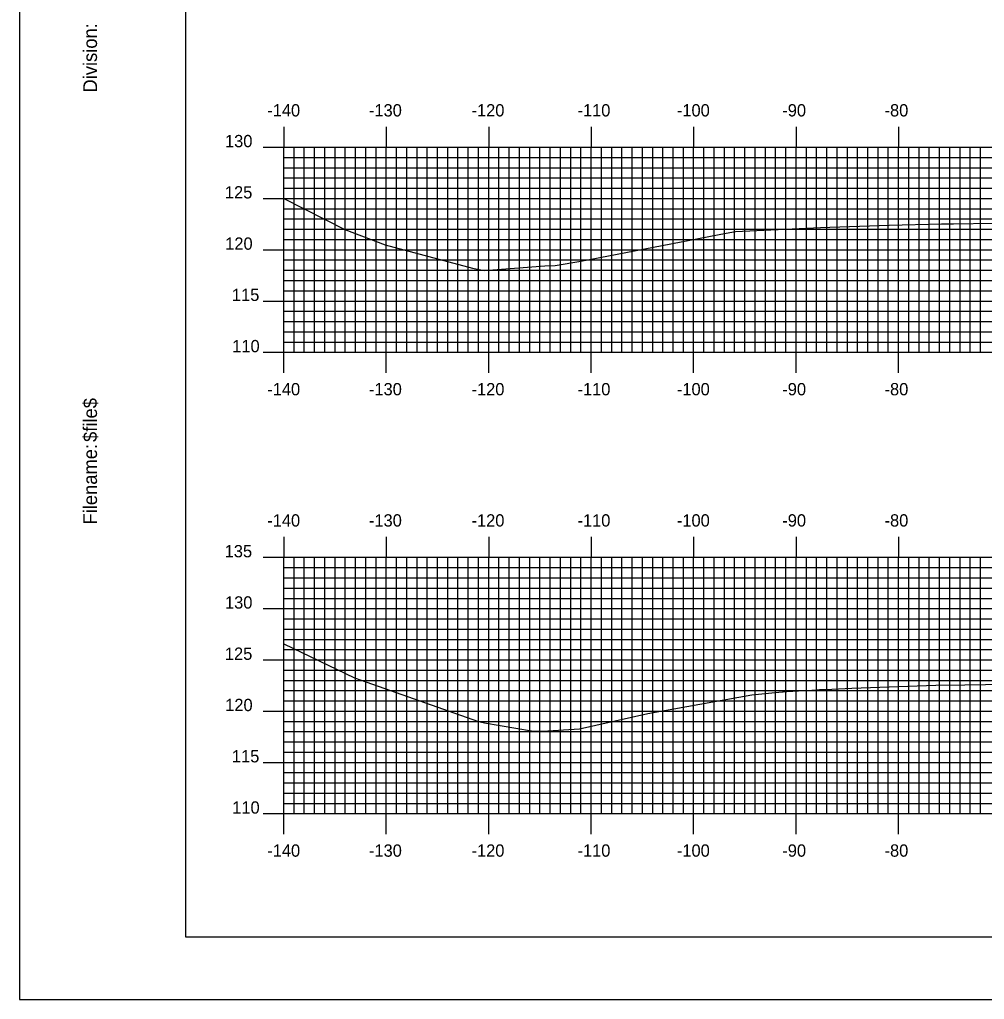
# Model space of a CAD drawing. Extents: x 853894 to 854237, y 366605 to 366825.
# Drawn here: x 853893.7 to 853987.9, y 366604.9 to 366700.5 of the extents above; entities that cross this region are included whole.
import ezdxf

# ---------------------------------------------------------------- set-up
doc = ezdxf.new("R2010")
doc.units = 0
for name, color, linetype in [('BORDER', 7, 'Continuous'), ('H_V ANNOTATION', 7, 'Continuous'), ('M_Roadway_Centerline', 7, 'Continuous'), ('MAJOR', 7, 'Continuous'), ('MINOR', 7, 'Continuous'), ('PLOT BOUNDARY', 7, 'Continuous'), ('S_Roadway_Centerline', 7, 'Continuous')]:
    doc.layers.add(name, color=color, linetype=linetype)

msp = doc.modelspace()

# ---------------------------------------------------------------- linework, layer by layer
at = {"layer": 'BORDER'}
msp.add_lwpolyline([(853909.93, 366611.055), (854229.93, 366611.055), (854229.93, 366821.055), (853909.93, 366821.055)], close=True, dxfattribs=at)
at = {"layer": 'MAJOR'}
for p, q in [((853919.53, 366690.059), (853919.53, 366688.055)), ((853929.53, 366690.059), (853929.53, 366688.055)), ((853939.53, 366690.059), (853939.53, 366688.055)), ((853949.53, 366690.059), (853949.53, 366688.055)), ((853959.53, 366690.059), (853959.53, 366688.055)), ((853969.53, 366690.059), (853969.53, 366688.055)), ((853979.53, 366690.059), (853979.53, 366688.055)), ((853917.526, 366688.055), (853919.53, 366688.055)), ((853919.53, 366688.055), (854199.53, 366688.055)), ((853919.53, 366668.055), (853919.53, 366688.055)), ((853919.53, 366668.055), (853919.53, 366688.055)), ((853919.53, 366688.055), (854199.53, 366688.055)), ((853929.53, 366668.055), (853929.53, 366688.055)), ((853939.53, 366668.055), (853939.53, 366688.055)), ((853949.53, 366668.055), (853949.53, 366688.055)), ((853959.53, 366668.055), (853959.53, 366688.055)), ((853969.53, 366668.055), (853969.53, 366688.055)), ((853979.53, 366668.055), (853979.53, 366688.055)), ((853917.526, 366683.055), (853919.53, 366683.055)), ((853919.53, 366683.055), (854199.53, 366683.055)), ((853917.526, 366678.055), (853919.53, 366678.055)), ((853919.53, 366678.055), (854199.53, 366678.055)), ((853917.526, 366673.055), (853919.53, 366673.055)), ((853919.53, 366673.055), (854199.53, 366673.055)), ((853917.526, 366668.055), (853919.53, 366668.055)), ((853919.53, 366668.055), (854199.53, 366668.055)), ((853919.53, 366668.055), (854199.53, 366668.055)), ((853919.53, 366666.051), (853919.53, 366668.055)), ((853929.53, 366666.051), (853929.53, 366668.055)), ((853939.53, 366666.051), (853939.53, 366668.055)), ((853949.53, 366666.051), (853949.53, 366668.055)), ((853959.53, 366666.051), (853959.53, 366668.055)), ((853969.53, 366666.051), (853969.53, 366668.055)), ((853979.53, 366666.051), (853979.53, 366668.055)), ((853919.53, 366650.059), (853919.53, 366648.055)), ((853929.53, 366650.059), (853929.53, 366648.055)), ((853939.53, 366650.059), (853939.53, 366648.055)), ((853949.53, 366650.059), (853949.53, 366648.055)), ((853959.53, 366650.059), (853959.53, 366648.055)), ((853969.53, 366650.059), (853969.53, 366648.055)), ((853979.53, 366650.059), (853979.53, 366648.055)), ((853917.526, 366648.055), (853919.53, 366648.055)), ((853919.53, 366648.055), (854199.53, 366648.055)), ((853919.53, 366623.055), (853919.53, 366648.055)), ((853919.53, 366623.055), (853919.53, 366648.055)), ((853919.53, 366648.055), (854199.53, 366648.055)), ((853929.53, 366623.055), (853929.53, 366648.055)), ((853939.53, 366623.055), (853939.53, 366648.055)), ((853949.53, 366623.055), (853949.53, 366648.055)), ((853959.53, 366623.055), (853959.53, 366648.055)), ((853969.53, 366623.055), (853969.53, 366648.055)), ((853979.53, 366623.055), (853979.53, 366648.055)), ((853917.526, 366643.055), (853919.53, 366643.055)), ((853919.53, 366643.055), (854199.53, 366643.055)), ((853917.526, 366638.055), (853919.53, 366638.055)), ((853919.53, 366638.055), (854199.53, 366638.055)), ((853917.526, 366633.055), (853919.53, 366633.055)), ((853919.53, 366633.055), (854199.53, 366633.055)), ((853917.526, 366628.055), (853919.53, 366628.055)), ((853919.53, 366628.055), (854199.53, 366628.055)), ((853917.526, 366623.055), (853919.53, 366623.055)), ((853919.53, 366623.055), (854199.53, 366623.055)), ((853919.53, 366623.055), (854199.53, 366623.055)), ((853919.53, 366621.051), (853919.53, 366623.055)), ((853929.53, 366621.051), (853929.53, 366623.055)), ((853939.53, 366621.051), (853939.53, 366623.055)), ((853949.53, 366621.051), (853949.53, 366623.055)), ((853959.53, 366621.051), (853959.53, 366623.055)), ((853969.53, 366621.051), (853969.53, 366623.055)), ((853979.53, 366621.051), (853979.53, 366623.055))]:
    msp.add_line(p, q, dxfattribs=at)
at = {"layer": 'MINOR'}
for p, q in [((853920.53, 366668.055), (853920.53, 366688.055)), ((853921.53, 366668.055), (853921.53, 366688.055)), ((853922.53, 366668.055), (853922.53, 366688.055)), ((853923.53, 366668.055), (853923.53, 366688.055)), ((853924.53, 366668.055), (853924.53, 366688.055)), ((853925.53, 366668.055), (853925.53, 366688.055)), ((853926.53, 366668.055), (853926.53, 366688.055)), ((853927.53, 366668.055), (853927.53, 366688.055)), ((853928.53, 366668.055), (853928.53, 366688.055)), ((853930.53, 366668.055), (853930.53, 366688.055)), ((853931.53, 366668.055), (853931.53, 366688.055)), ((853932.53, 366668.055), (853932.53, 366688.055)), ((853933.53, 366668.055), (853933.53, 366688.055)), ((853934.53, 366668.055), (853934.53, 366688.055)), ((853935.53, 366668.055), (853935.53, 366688.055)), ((853936.53, 366668.055), (853936.53, 366688.055)), ((853937.53, 366668.055), (853937.53, 366688.055)), ((853938.53, 366668.055), (853938.53, 366688.055)), ((853940.53, 366668.055), (853940.53, 366688.055)), ((853941.53, 366668.055), (853941.53, 366688.055)), ((853942.53, 366668.055), (853942.53, 366688.055)), ((853943.53, 366668.055), (853943.53, 366688.055)), ((853944.53, 366668.055), (853944.53, 366688.055)), ((853945.53, 366668.055), (853945.53, 366688.055)), ((853946.53, 366668.055), (853946.53, 366688.055)), ((853947.53, 366668.055), (853947.53, 366688.055)), ((853948.53, 366668.055), (853948.53, 366688.055)), ((853950.53, 366668.055), (853950.53, 366688.055)), ((853951.53, 366668.055), (853951.53, 366688.055)), ((853952.53, 366668.055), (853952.53, 366688.055)), ((853953.53, 366668.055), (853953.53, 366688.055)), ((853954.53, 366668.055), (853954.53, 366688.055)), ((853955.53, 366668.055), (853955.53, 366688.055)), ((853956.53, 366668.055), (853956.53, 366688.055)), ((853957.53, 366668.055), (853957.53, 366688.055)), ((853958.53, 366668.055), (853958.53, 366688.055)), ((853960.53, 366668.055), (853960.53, 366688.055)), ((853961.53, 366668.055), (853961.53, 366688.055)), ((853962.53, 366668.055), (853962.53, 366688.055)), ((853963.53, 366668.055), (853963.53, 366688.055)), ((853964.53, 366668.055), (853964.53, 366688.055)), ((853965.53, 366668.055), (853965.53, 366688.055)), ((853966.53, 366668.055), (853966.53, 366688.055)), ((853967.53, 366668.055), (853967.53, 366688.055)), ((853968.53, 366668.055), (853968.53, 366688.055)), ((853970.53, 366668.055), (853970.53, 366688.055)), ((853971.53, 366668.055), (853971.53, 366688.055)), ((853972.53, 366668.055), (853972.53, 366688.055)), ((853973.53, 366668.055), (853973.53, 366688.055)), ((853974.53, 366668.055), (853974.53, 366688.055)), ((853975.53, 366668.055), (853975.53, 366688.055)), ((853976.53, 366668.055), (853976.53, 366688.055)), ((853977.53, 366668.055), (853977.53, 366688.055)), ((853978.53, 366668.055), (853978.53, 366688.055)), ((853980.53, 366668.055), (853980.53, 366688.055)), ((853981.53, 366668.055), (853981.53, 366688.055)), ((853982.53, 366668.055), (853982.53, 366688.055)), ((853983.53, 366668.055), (853983.53, 366688.055)), ((853984.53, 366668.055), (853984.53, 366688.055)), ((853985.53, 366668.055), (853985.53, 366688.055)), ((853986.53, 366668.055), (853986.53, 366688.055)), ((853987.53, 366668.055), (853987.53, 366688.055)), ((853919.53, 366687.055), (854199.53, 366687.055)), ((853919.53, 366687.055), (853921.534, 366687.055)), ((853919.53, 366686.055), (854199.53, 366686.055)), ((853919.53, 366686.055), (853921.534, 366686.055)), ((853919.53, 366685.055), (854199.53, 366685.055)), ((853919.53, 366685.055), (853921.534, 366685.055)), ((853919.53, 366684.055), (854199.53, 366684.055)), ((853919.53, 366684.055), (853921.534, 366684.055)), ((853919.53, 366682.055), (854199.53, 366682.055)), ((853919.53, 366682.055), (853921.534, 366682.055)), ((853919.53, 366681.055), (854199.53, 366681.055)), ((853919.53, 366681.055), (853921.534, 366681.055)), ((853919.53, 366680.055), (854199.53, 366680.055)), ((853919.53, 366680.055), (853921.534, 366680.055)), ((853919.53, 366679.055), (854199.53, 366679.055)), ((853919.53, 366679.055), (853921.534, 366679.055)), ((853919.53, 366677.055), (854199.53, 366677.055)), ((853919.53, 366677.055), (853921.534, 366677.055)), ((853919.53, 366676.055), (854199.53, 366676.055)), ((853919.53, 366676.055), (853921.534, 366676.055)), ((853919.53, 366675.055), (854199.53, 366675.055)), ((853919.53, 366675.055), (853921.534, 366675.055)), ((853919.53, 366674.055), (854199.53, 366674.055)), ((853919.53, 366674.055), (853921.534, 366674.055)), ((853919.53, 366672.055), (854199.53, 366672.055)), ((853919.53, 366672.055), (853921.534, 366672.055)), ((853919.53, 366671.055), (854199.53, 366671.055)), ((853919.53, 366671.055), (853921.534, 366671.055)), ((853919.53, 366670.055), (854199.53, 366670.055)), ((853919.53, 366670.055), (853921.534, 366670.055)), ((853919.53, 366669.055), (854199.53, 366669.055)), ((853919.53, 366669.055), (853921.534, 366669.055)), ((853920.53, 366623.055), (853920.53, 366648.055)), ((853921.53, 366623.055), (853921.53, 366648.055)), ((853922.53, 366623.055), (853922.53, 366648.055)), ((853923.53, 366623.055), (853923.53, 366648.055)), ((853924.53, 366623.055), (853924.53, 366648.055)), ((853925.53, 366623.055), (853925.53, 366648.055)), ((853926.53, 366623.055), (853926.53, 366648.055)), ((853927.53, 366623.055), (853927.53, 366648.055)), ((853928.53, 366623.055), (853928.53, 366648.055)), ((853930.53, 366623.055), (853930.53, 366648.055)), ((853931.53, 366623.055), (853931.53, 366648.055)), ((853932.53, 366623.055), (853932.53, 366648.055)), ((853933.53, 366623.055), (853933.53, 366648.055)), ((853934.53, 366623.055), (853934.53, 366648.055)), ((853935.53, 366623.055), (853935.53, 366648.055)), ((853936.53, 366623.055), (853936.53, 366648.055)), ((853937.53, 366623.055), (853937.53, 366648.055)), ((853938.53, 366623.055), (853938.53, 366648.055)), ((853940.53, 366623.055), (853940.53, 366648.055)), ((853941.53, 366623.055), (853941.53, 366648.055)), ((853942.53, 366623.055), (853942.53, 366648.055)), ((853943.53, 366623.055), (853943.53, 366648.055)), ((853944.53, 366623.055), (853944.53, 366648.055)), ((853945.53, 366623.055), (853945.53, 366648.055)), ((853946.53, 366623.055), (853946.53, 366648.055)), ((853947.53, 366623.055), (853947.53, 366648.055)), ((853948.53, 366623.055), (853948.53, 366648.055)), ((853950.53, 366623.055), (853950.53, 366648.055)), ((853951.53, 366623.055), (853951.53, 366648.055)), ((853952.53, 366623.055), (853952.53, 366648.055)), ((853953.53, 366623.055), (853953.53, 366648.055)), ((853954.53, 366623.055), (853954.53, 366648.055)), ((853955.53, 366623.055), (853955.53, 366648.055)), ((853956.53, 366623.055), (853956.53, 366648.055)), ((853957.53, 366623.055), (853957.53, 366648.055)), ((853958.53, 366623.055), (853958.53, 366648.055)), ((853960.53, 366623.055), (853960.53, 366648.055)), ((853961.53, 366623.055), (853961.53, 366648.055)), ((853962.53, 366623.055), (853962.53, 366648.055)), ((853963.53, 366623.055), (853963.53, 366648.055)), ((853964.53, 366623.055), (853964.53, 366648.055)), ((853965.53, 366623.055), (853965.53, 366648.055)), ((853966.53, 366623.055), (853966.53, 366648.055)), ((853967.53, 366623.055), (853967.53, 366648.055)), ((853968.53, 366623.055), (853968.53, 366648.055)), ((853970.53, 366623.055), (853970.53, 366648.055)), ((853971.53, 366623.055), (853971.53, 366648.055)), ((853972.53, 366623.055), (853972.53, 366648.055)), ((853973.53, 366623.055), (853973.53, 366648.055)), ((853974.53, 366623.055), (853974.53, 366648.055)), ((853975.53, 366623.055), (853975.53, 366648.055)), ((853976.53, 366623.055), (853976.53, 366648.055)), ((853977.53, 366623.055), (853977.53, 366648.055)), ((853978.53, 366623.055), (853978.53, 366648.055)), ((853980.53, 366623.055), (853980.53, 366648.055)), ((853981.53, 366623.055), (853981.53, 366648.055)), ((853982.53, 366623.055), (853982.53, 366648.055)), ((853983.53, 366623.055), (853983.53, 366648.055)), ((853984.53, 366623.055), (853984.53, 366648.055)), ((853985.53, 366623.055), (853985.53, 366648.055)), ((853986.53, 366623.055), (853986.53, 366648.055)), ((853987.53, 366623.055), (853987.53, 366648.055)), ((853919.53, 366647.055), (854199.53, 366647.055)), ((853919.53, 366647.055), (853921.534, 366647.055)), ((853919.53, 366646.055), (854199.53, 366646.055)), ((853919.53, 366646.055), (853921.534, 366646.055)), ((853919.53, 366645.055), (854199.53, 366645.055)), ((853919.53, 366645.055), (853921.534, 366645.055)), ((853919.53, 366644.055), (854199.53, 366644.055)), ((853919.53, 366644.055), (853921.534, 366644.055)), ((853919.53, 366642.055), (854199.53, 366642.055)), ((853919.53, 366642.055), (853921.534, 366642.055)), ((853919.53, 366641.055), (854199.53, 366641.055)), ((853919.53, 366641.055), (853921.534, 366641.055)), ((853919.53, 366640.055), (854199.53, 366640.055)), ((853919.53, 366640.055), (853921.534, 366640.055)), ((853919.53, 366639.055), (854199.53, 366639.055)), ((853919.53, 366639.055), (853921.534, 366639.055)), ((853919.53, 366637.055), (854199.53, 366637.055)), ((853919.53, 366637.055), (853921.534, 366637.055)), ((853919.53, 366636.055), (854199.53, 366636.055)), ((853919.53, 366636.055), (853921.534, 366636.055)), ((853919.53, 366635.055), (854199.53, 366635.055)), ((853919.53, 366635.055), (853921.534, 366635.055)), ((853919.53, 366634.055), (854199.53, 366634.055)), ((853919.53, 366634.055), (853921.534, 366634.055)), ((853919.53, 366632.055), (854199.53, 366632.055)), ((853919.53, 366632.055), (853921.534, 366632.055)), ((853919.53, 366631.055), (854199.53, 366631.055)), ((853919.53, 366631.055), (853921.534, 366631.055)), ((853919.53, 366630.055), (854199.53, 366630.055)), ((853919.53, 366630.055), (853921.534, 366630.055)), ((853919.53, 366629.055), (854199.53, 366629.055)), ((853919.53, 366629.055), (853921.534, 366629.055)), ((853919.53, 366627.055), (854199.53, 366627.055)), ((853919.53, 366627.055), (853921.534, 366627.055)), ((853919.53, 366626.055), (854199.53, 366626.055)), ((853919.53, 366626.055), (853921.534, 366626.055)), ((853919.53, 366625.055), (854199.53, 366625.055)), ((853919.53, 366625.055), (853921.534, 366625.055)), ((853919.53, 366624.055), (854199.53, 366624.055)), ((853919.53, 366624.055), (853921.534, 366624.055))]:
    msp.add_line(p, q, dxfattribs=at)
at = {"layer": 'PLOT BOUNDARY'}
msp.add_lwpolyline([(853893.743, 366604.937), (854233.743, 366604.937), (854233.743, 366824.937), (853893.743, 366824.937)], close=True, dxfattribs=at)
at = {"layer": 'S_Roadway_Centerline'}
for points in [[(853919.53, 366683.041), (853925.476, 366680.031), (853929.425, 366678.531), (853937.932, 366676.27), (853939.079, 366676.03), (853944.991, 366676.484), (853946.023, 366676.528), (853948.521, 366676.946), (853962.69, 366679.679), (853963.606, 366679.835), (853965.702, 366679.918), (853971.915, 366680.235), (853972.806, 366680.263), (853978.623, 366680.437), (853983.733, 366680.567), (853983.821, 366680.57), (853984.895, 366680.569), (853988.77, 366680.635)], [(853919.53, 366639.614), (853926.419, 366636.286), (853938.545, 366632.052), (853939.105, 366631.907), (853943.713, 366631.117), (853944.786, 366631.088), (853948.393, 366631.325), (853955.055, 366632.811), (853965.214, 366634.652), (853967.174, 366634.822), (853968.201, 366634.938), (853968.267, 366634.944), (853968.5, 366634.957), (853968.615, 366634.964), (853970.334, 366635.066), (853971.079, 366635.106), (853971.593, 366635.135), (853971.82, 366635.15), (853972.36, 366635.165), (853974.969, 366635.298), (853981.357, 366635.529), (853983.177, 366635.595), (853983.179, 366635.6), (853985.984, 366635.626), (853994.07, 366635.744)]]:
    msp.add_lwpolyline(points, dxfattribs=at)

# ---------------------------------------------------------------- texts
at = {"layer": 'BORDER'}
for s, p in [('Division:', (853901.3, 366693.387)), ('$file$', (853901.3, 366659.306)), ('Filename:', (853901.3, 366651.252))]:
    msp.add_text(s, height=1.3392, rotation=90, dxfattribs=at).set_placement(p)
at = {"layer": 'H_V ANNOTATION'}
for s, p in [('-140', (853917.914, 366691.055)), ('-130', (853927.839, 366691.055)), ('-120', (853937.85, 366691.055)), ('-110', (853948.192, 366691.055)), ('-100', (853957.892, 366691.055)), ('-90', (853968.181, 366691.055)), ('-80', (853978.16, 366691.055)), ('130', (853913.79, 366688.055)), ('125', (853913.779, 366683.055)), ('120', (853913.811, 366678.055)), ('115', (853914.465, 366673.055)), ('110', (853914.497, 366668.055)), ('-140', (853917.914, 366663.855)), ('-130', (853927.839, 366663.855)), ('-120', (853937.85, 366663.855)), ('-110', (853948.192, 366663.855)), ('-100', (853957.892, 366663.855)), ('-90', (853968.181, 366663.855)), ('-80', (853978.16, 366663.855)), ('-140', (853917.914, 366651.055)), ('-130', (853927.839, 366651.055)), ('-120', (853937.85, 366651.055)), ('-110', (853948.192, 366651.055)), ('-100', (853957.892, 366651.055)), ('-90', (853968.181, 366651.055)), ('-80', (853978.16, 366651.055)), ('135', (853913.758, 366648.055)), ('130', (853913.79, 366643.055)), ('125', (853913.779, 366638.055)), ('120', (853913.811, 366633.055)), ('115', (853914.465, 366628.055)), ('110', (853914.497, 366623.055)), ('-140', (853917.914, 366618.855)), ('-130', (853927.839, 366618.855)), ('-120', (853937.85, 366618.855)), ('-110', (853948.192, 366618.855)), ('-100', (853957.892, 366618.855)), ('-90', (853968.181, 366618.855)), ('-80', (853978.16, 366618.855))]:
    msp.add_text(s, height=1.2, dxfattribs=at).set_placement(p)
at = {"layer": 'M_Roadway_Centerline'}
for s, p in [('C', (853978.617, 366680.437)), ('L', (853978.623, 366680.429)), ('C', (853983.173, 366635.6)), ('L', (853983.179, 366635.593))]:
    msp.add_text(s, height=0.0146, dxfattribs=at).set_placement(p)
at = {"layer": 'MAJOR'}
for p in [(853919.521, 366668.055), (853919.521, 366623.055)]:
    msp.add_text('-', height=0.012, dxfattribs=at).set_placement(p)

doc.saveas('drawing.dxf')
